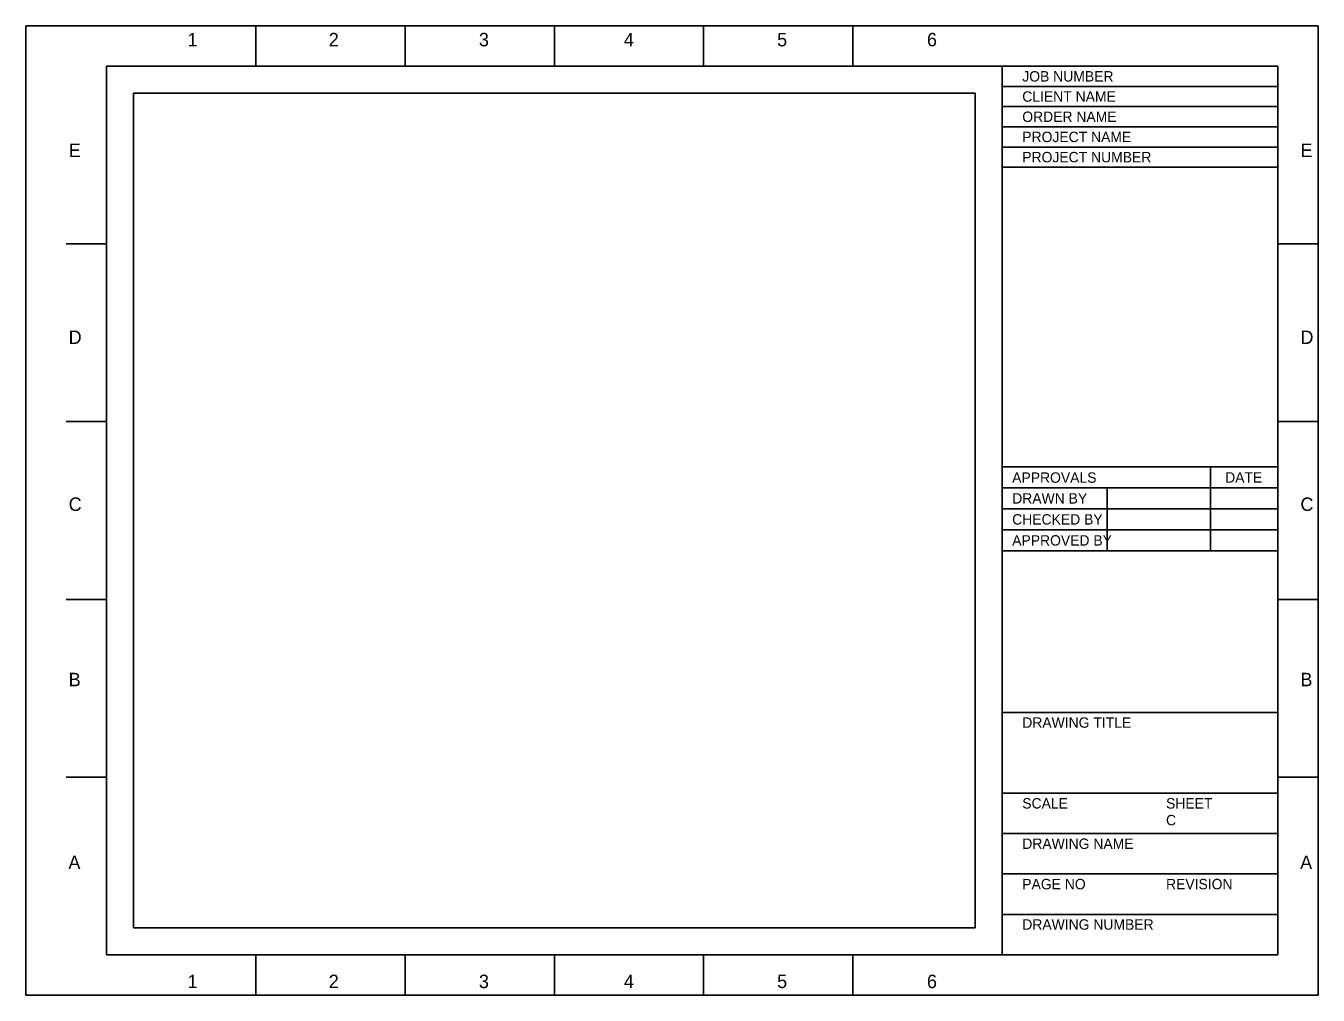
# Model space of a CAD drawing. Extents: x 0 to 2, y 0 to 1.5.
import ezdxf

# ---------------------------------------------------------------- set-up
doc = ezdxf.new("R2010")
doc.units = 0
for name, color, linetype in [('Border', 7, 'Continuous'), ('BorderPlot', 7, 'Continuous'), ('ClipShape', 7, 'Continuous'), ('STSF-BORDER', 7, 'Continuous'), ('TitleBlock', 7, 'Continuous')]:
    doc.layers.add(name, color=color, linetype=linetype)

# ---------------------------------------------------------------- blocks, each defined once
blk = doc.blocks.new('DC-ARCH-C')
at = {"layer": 'Border'}
for p, q in [((0.356, 1.4375), (0.356, 1.5)), ((0.5869, 1.4375), (0.5869, 1.5)), ((0.8179, 1.4375), (0.8179, 1.5)), ((1.0489, 1.4375), (1.0489, 1.5)), ((1.2799, 1.4375), (1.2799, 1.5)), ((1.5108, 1.4375), (1.5108, 0.0625)), ((0.125, 1.1625), (0.0625, 1.1625)), ((1.9375, 1.1625), (2, 1.1625)), ((0.125, 0.8875), (0.0625, 0.8875)), ((1.9375, 0.8875), (2, 0.8875)), ((0.125, 0.6125), (0.0625, 0.6125)), ((1.9375, 0.6125), (2, 0.6125)), ((0.125, 0.3375), (0.0625, 0.3375)), ((1.9375, 0.3375), (2, 0.3375)), ((0.356, 0.0625), (0.356, 0)), ((0.5869, 0.0625), (0.5869, 0)), ((0.8179, 0.0625), (0.8179, 0)), ((1.0489, 0.0625), (1.0489, 0)), ((1.2799, 0.0625), (1.2799, 0))]:
    blk.add_line(p, q, dxfattribs=at)
blk.add_lwpolyline([(1.9375, 0.0625), (0.125, 0.0625), (0.125, 1.4375), (1.9375, 1.4375)], close=True, dxfattribs=at)
at = {"layer": 'BorderPlot'}
blk.add_lwpolyline([(0, 1.5), (2, 1.5), (2, 0), (0, 0)], close=True, dxfattribs=at)
at = {"layer": 'ClipShape'}
for p, q in [((0.1667, 0.1042), (0.1667, 1.3958)), ((0.1667, 1.3958), (1.4692, 1.3958)), ((1.4692, 1.3958), (1.4692, 0.1042)), ((1.4692, 0.1042), (0.1667, 0.1042))]:
    blk.add_line(p, q, dxfattribs=at)
at = {"layer": 'TitleBlock'}
for p, q in [((1.5108, 1.4062), (1.9375, 1.4062)), ((1.5108, 1.375), (1.9375, 1.375)), ((1.5108, 1.375), (1.9375, 1.375)), ((1.5108, 1.3437), (1.9375, 1.3437)), ((1.5108, 1.3125), (1.9375, 1.3125)), ((1.5108, 1.3125), (1.9375, 1.3125)), ((1.5108, 1.2812), (1.9375, 1.2812)), ((1.5108, 0.8174), (1.9375, 0.8174)), ((1.8332, 0.6875), (1.8332, 0.8174)), ((1.5108, 0.7849), (1.9375, 0.7849)), ((1.6736, 0.6875), (1.6736, 0.7849)), ((1.5108, 0.7525), (1.9375, 0.7525)), ((1.5108, 0.72), (1.9375, 0.72)), ((1.5108, 0.6875), (1.9375, 0.6875)), ((1.5108, 0.4375), (1.9375, 0.4375)), ((1.5108, 0.3125), (1.9375, 0.3125)), ((1.5108, 0.25), (1.9375, 0.25)), ((1.5108, 0.25), (1.9375, 0.25)), ((1.5108, 0.1875), (1.9375, 0.1875)), ((1.5108, 0.1875), (1.9375, 0.1875)), ((1.5108, 0.125), (1.9375, 0.125)), ((1.9375, 0.0625), (1.9375, 0.0625))]:
    blk.add_line(p, q, dxfattribs=at)
at = {"layer": 'Border'}
for s, p in [('1', (0.2504, 1.4683)), ('2', (0.4688, 1.4683)), ('3', (0.7012, 1.4683)), ('4', (0.9255, 1.4683)), ('5', (1.1627, 1.4683)), ('6', (1.3946, 1.4683)), ('E', (0.0664, 1.297)), ('E', (1.9727, 1.297)), ('D', (0.0663, 1.0077)), ('D', (1.9726, 1.0077)), ('C', (0.0663, 0.7493)), ('C', (1.9726, 0.7493)), ('B', (0.0663, 0.478)), ('B', (1.9726, 0.478)), ('A', (0.0659, 0.1952)), ('A', (1.9722, 0.1952)), ('1', (0.2504, 0.0109)), ('2', (0.4688, 0.0109)), ('3', (0.7012, 0.0109)), ('4', (0.9255, 0.0109)), ('5', (1.1627, 0.0109)), ('6', (1.3946, 0.0109))]:
    blk.add_text(s, height=0.0208, dxfattribs=at).set_placement(p)
at = {"layer": 'STSF-BORDER'}
for s, height, p in [('JOB NUMBER', 0.0161, (1.5421, 1.4138)), ('CLIENT NAME', 0.016098, (1.5421, 1.3826)), ('ORDER NAME', 0.0161, (1.5421, 1.3513)), ('PROJECT NAME', 0.016098, (1.5421, 1.3201)), ('PROJECT NUMBER', 0.016098, (1.5421, 1.2888)), ('APPROVALS', 0.0161, (1.5265, 0.7929)), ('DATE', 0.0161, (1.8561, 0.7931)), ('DRAWN BY', 0.0161, (1.5265, 0.7607)), ('CHECKED BY', 0.0161, (1.5265, 0.7282)), ('APPROVED BY', 0.016098, (1.5265, 0.6957)), ('DRAWING TITLE', 0.016098, (1.5421, 0.4138)), ('SCALE', 0.0161, (1.5421, 0.2888)), ('SHEET', 0.0161, (1.7646, 0.2888)), ('C', 0.0161, (1.7646, 0.2628)), ('DRAWING NAME', 0.016098, (1.5421, 0.2263)), ('PAGE NO', 0.0161, (1.5421, 0.1638)), ('REVISION', 0.0161, (1.7646, 0.1638)), ('DRAWING NUMBER', 0.016098, (1.5421, 0.1013))]:
    blk.add_text(s, height=height, dxfattribs=at).set_placement(p)

msp = doc.modelspace()

# ---------------------------------------------------------------- block references
msp.add_blockref('DC-ARCH-C', (0, 0))

doc.saveas('drawing.dxf')
